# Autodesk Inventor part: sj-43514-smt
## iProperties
Created: 2016-03
Part Number: sj-43514-smt
Checked By: TraceParts S.A.
Catalog Web Link: www.traceparts.com
Document SubType Name: Modeling
Designer: TraceParts
Density: 1 g/cm^3
Company: TraceParts S.A.
Author: TraceParts
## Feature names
1. sj-43514-smt
